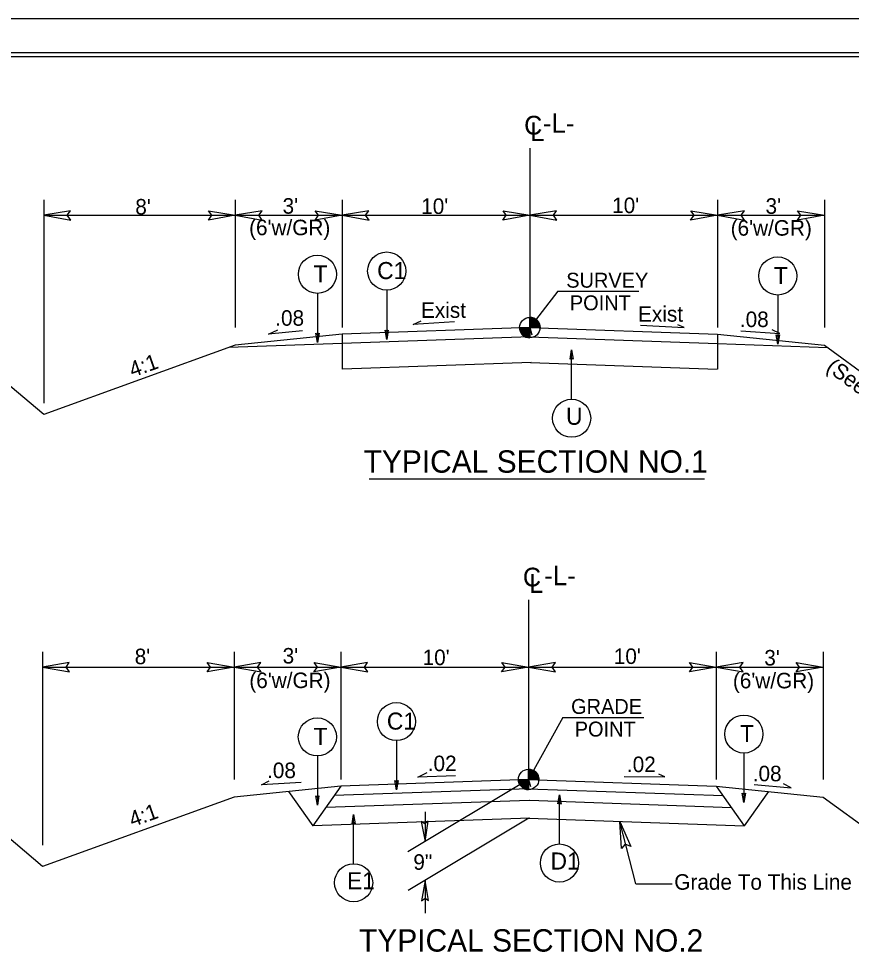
# Model space of a CAD drawing. Extents: x 573693 to 575619, y -55388 to -54288.
# Drawn here: x 574388 to 574934, y -54903 to -54288 of the extents above; entities that cross this region are included whole.
import ezdxf

# ---------------------------------------------------------------- set-up
doc = ezdxf.new("R2010")
doc.units = 0
for name, color, linetype in [('Default', 7, 'Continuous'), ('Prop Dimension', 7, 'Continuous'), ('Sheet Border Standard 30in CELL', 7, 'Continuous'), ('Sheet Cutting Line CELL', 7, 'Continuous'), ('Sheet Plot Border Inside CELL', 7, 'Continuous'), ('Sheet Plot Border Outside CELL', 7, 'Continuous'), ('Typical Grade Point Symbol CELL', 7, 'Continuous'), ('Typical ID Circle CELL', 7, 'Continuous'), ('Typical Terminator CELL', 7, 'Continuous'), ('Typical Text Centerline CELL', 7, 'Continuous'), ('Typical Text Grade Point CELL', 7, 'Continuous'), ('Typical Text ID Circle CELL', 7, 'Continuous')]:
    doc.layers.add(name, color=color, linetype=linetype)

msp = doc.modelspace()

# ---------------------------------------------------------------- linework, layer by layer
at = {"layer": 'Default'}
for p, q in [((574722.78, -54373.26), (574722.78, -54490.98)), ((574403.92, -54407.2), (574403.92, -54540.5)), ((574529.59, -54407.2), (574529.59, -54490.98)), ((574599.64, -54407.2), (574599.64, -54490.98)), ((574845.92, -54407.2), (574845.92, -54490.98)), ((574915.98, -54407.2), (574915.98, -54490.98)), ((574403.92, -54417.32), (574529.59, -54417.32)), ((574529.59, -54417.32), (574599.64, -54417.32)), ((574599.64, -54417.32), (574722.78, -54417.32)), ((574722.78, -54417.32), (574845.92, -54417.32)), ((574845.92, -54417.32), (574915.98, -54417.32)), ((574722.78, -54490.98), (574724.07, -54495.66)), ((574721.96, -54669.68), (574721.96, -54787.4)), ((574403.1, -54703.62), (574403.1, -54830.51)), ((574528.77, -54703.62), (574528.77, -54787.4)), ((574598.82, -54703.62), (574598.82, -54787.4)), ((574845.1, -54703.62), (574845.1, -54787.4)), ((574915.16, -54703.62), (574915.16, -54787.4)), ((574403.1, -54713.73), (574528.77, -54713.73)), ((574528.77, -54713.73), (574598.82, -54713.73)), ((574598.82, -54713.73), (574721.96, -54713.73)), ((574721.96, -54713.73), (574845.1, -54713.73)), ((574845.1, -54713.73), (574915.16, -54713.73)), ((574721.96, -54787.4), (574642.72, -54834.92)), ((574721.96, -54787.4), (574723.25, -54792.07)), ((574654.06, -54808.55), (574654.06, -54828.12)), ((574722.2, -54812.85), (574642.95, -54860.37)), ((574654.06, -54853.71), (574654.06, -54875.21))]:
    msp.add_line(p, q, dxfattribs=at)
at = {"layer": 'Prop Dimension'}
for p, q in [((574403.92, -54548.04), (574330.25, -54485.93)), ((574599.64, -54495.32), (574529.59, -54502.54)), ((574722.78, -54490.98), (574599.64, -54495.32)), ((574599.64, -54495.32), (574599.66, -54501.45)), ((574722.78, -54490.98), (574845.92, -54495.32)), ((574845.92, -54495.32), (574915.98, -54502.54)), ((574845.92, -54495.32), (574845.93, -54501.45)), ((574599.66, -54501.45), (574525.37, -54504.06)), ((574723, -54497.11), (574599.66, -54501.45)), ((574599.66, -54501.45), (574599.71, -54518.24)), ((574722.57, -54497.1), (574845.93, -54501.44)), ((574845.92, -54501.44), (574845.92, -54518.19)), ((574845.92, -54501.44), (574917.94, -54503.97)), ((574529.59, -54502.54), (574403.92, -54548.04)), ((574915.98, -54502.54), (575050.31, -54600.76)), ((574723.59, -54513.88), (574599.92, -54518.23)), ((574723.11, -54513.86), (574845.68, -54518.18)), ((574617.38, -54590.24), (574837.3, -54590.24)), ((574403.1, -54844.45), (574329.43, -54782.34)), ((574721.96, -54787.4), (574598.82, -54791.73)), ((574721.96, -54787.4), (574845.1, -54791.73)), ((574598.82, -54791.73), (574528.77, -54798.95)), ((574564.56, -54795.26), (574580.45, -54817.84)), ((574598.82, -54791.73), (574580.45, -54817.84)), ((574722.18, -54793.53), (574594.4, -54798.02)), ((574721.75, -54793.51), (574849.52, -54798.01)), ((574845.1, -54791.73), (574915.16, -54798.95)), ((574845.1, -54791.73), (574863.46, -54817.82)), ((574879.34, -54795.26), (574863.46, -54817.82)), ((574528.77, -54798.95), (574403.1, -54844.45)), ((574722.44, -54801.12), (574588.91, -54805.81)), ((574722.61, -54801.11), (574854.98, -54805.77)), ((574915.16, -54798.95), (575049.49, -54897.18)), ((574722.86, -54812.83), (574580.45, -54817.84)), ((574722.2, -54812.85), (574863.46, -54817.82)), ((574792.41, -54855.9), (574781.77, -54814.95)), ((574792.41, -54855.9), (574816.07, -54855.9))]:
    msp.add_line(p, q, dxfattribs=at)
at = {"layer": 'Sheet Border Standard 30in CELL'}
msp.add_lwpolyline([(575359.97, -54313.39), (573859.97, -54313.39), (573859.97, -55363.39), (575359.97, -55363.39)], close=True, dxfattribs=at)
at = {"layer": 'Sheet Cutting Line CELL'}
msp.add_line((575376.97, -54288.39), (573692.97, -54288.39), dxfattribs=at)
at = {"layer": 'Sheet Plot Border Inside CELL'}
msp.add_lwpolyline([(575372.47, -54310.84), (573705.97, -54310.84), (573705.97, -55365.94), (575372.47, -55365.94)], close=True, dxfattribs=at)
at = {"layer": 'Sheet Plot Border Outside CELL'}
msp.add_lwpolyline([(575376.97, -54288.39), (573692.97, -54288.39), (573692.97, -55388.39), (575376.97, -55388.39)], close=True, dxfattribs=at)
at = {"layer": 'Typical Grade Point Symbol CELL'}
for p, q in [((574722.78, -54490.98), (574722.78, -54484.27)), ((574716.07, -54490.98), (574722.78, -54490.98)), ((574722.77, -54497.7), (574722.78, -54490.98)), ((574722.78, -54490.98), (574722.77, -54497.7)), ((574729.5, -54490.98), (574722.78, -54490.98)), ((574721.96, -54787.4), (574721.96, -54780.68)), ((574715.25, -54787.4), (574721.96, -54787.4)), ((574721.95, -54794.11), (574721.96, -54787.4)), ((574721.96, -54787.4), (574721.95, -54794.11)), ((574728.67, -54787.4), (574721.96, -54787.4))]:
    msp.add_line(p, q, dxfattribs=at)
for points in [[(574722.84, -54484.27), (574722.84, -54484.27), (574722.84, -54490.98)], [(574722.98, -54484.27), (574722.98, -54490.98)], [(574723.11, -54484.28), (574723.11, -54490.98)], [(574723.25, -54484.28), (574723.25, -54490.98)], [(574723.38, -54484.3), (574723.38, -54490.98)], [(574723.51, -54484.31), (574723.51, -54490.98)], [(574723.65, -54484.33), (574723.65, -54490.98)], [(574723.78, -54484.34), (574723.78, -54490.98)], [(574723.92, -54484.36), (574723.92, -54490.98)], [(574724.05, -54484.39), (574724.05, -54490.98)], [(574724.19, -54484.42), (574724.19, -54490.98)], [(574724.32, -54484.45), (574724.32, -54490.98)], [(574724.45, -54484.48), (574724.45, -54490.98)], [(574724.59, -54484.52), (574724.59, -54490.98)], [(574724.72, -54484.55), (574724.72, -54490.98)], [(574724.86, -54484.6), (574724.86, -54490.98)], [(574724.99, -54484.64), (574724.99, -54490.98)], [(574725.13, -54484.69), (574725.13, -54490.98)], [(574725.26, -54484.75), (574725.26, -54490.98)], [(574725.39, -54484.81), (574725.39, -54490.98)], [(574725.53, -54484.87), (574725.53, -54490.98)], [(574725.66, -54484.92), (574725.66, -54490.98)], [(574725.8, -54484.98), (574725.8, -54490.98)], [(574725.93, -54485.06), (574725.93, -54490.98)], [(574726.07, -54485.13), (574726.07, -54490.98)], [(574726.2, -54485.21), (574726.2, -54490.98)], [(574726.33, -54485.28), (574726.33, -54490.98)], [(574726.47, -54485.37), (574726.47, -54490.98)], [(574726.6, -54485.46), (574726.6, -54490.98)], [(574726.74, -54485.57), (574726.74, -54490.98)], [(574726.87, -54485.66), (574726.87, -54490.98)], [(574727.01, -54485.76), (574727.01, -54490.98)], [(574727.14, -54485.88), (574727.14, -54490.98)], [(574727.27, -54486), (574727.27, -54490.98)], [(574727.41, -54486.12), (574727.41, -54490.98)], [(574727.54, -54486.25), (574727.54, -54490.98)], [(574727.68, -54486.39), (574727.68, -54490.98)], [(574727.81, -54486.54), (574727.81, -54490.98)], [(574727.95, -54486.7), (574727.95, -54490.98)], [(574728.08, -54486.86), (574728.08, -54490.98)], [(574728.21, -54487.04), (574728.21, -54490.98)], [(574728.35, -54487.24), (574728.35, -54490.98)], [(574728.48, -54487.45), (574728.48, -54490.98)], [(574728.62, -54487.67), (574728.62, -54490.98)], [(574728.75, -54487.91), (574728.75, -54490.98)], [(574728.88, -54488.19), (574728.88, -54490.98)], [(574729.02, -54488.51), (574729.02, -54490.98)], [(574729.15, -54488.88), (574729.15, -54490.98)], [(574729.29, -54489.34), (574729.29, -54490.98)], [(574716.1, -54490.98), (574716.1, -54491.71)], [(574716.23, -54490.98), (574716.23, -54492.5)], [(574716.37, -54490.98), (574716.37, -54492.98)], [(574716.5, -54490.98), (574716.5, -54493.38)], [(574716.64, -54490.98), (574716.64, -54493.7)], [(574716.77, -54490.98), (574716.77, -54493.98)], [(574716.9, -54490.98), (574716.9, -54494.23)], [(574717.04, -54490.98), (574717.04, -54494.47)], [(574717.17, -54490.98), (574717.17, -54494.68)], [(574717.31, -54490.98), (574717.31, -54494.88)], [(574717.44, -54490.98), (574717.44, -54495.06)], [(574717.58, -54490.98), (574717.58, -54495.22)], [(574717.71, -54490.98), (574717.71, -54495.38)], [(574717.84, -54490.98), (574717.84, -54495.53)], [(574717.98, -54490.98), (574717.98, -54495.68)], [(574718.11, -54490.98), (574718.11, -54495.82)], [(574718.25, -54490.98), (574718.25, -54495.94)], [(574718.38, -54490.98), (574718.38, -54496.06)], [(574718.52, -54490.98), (574718.52, -54496.17)], [(574718.65, -54490.98), (574718.65, -54496.28)], [(574718.78, -54490.98), (574718.78, -54496.38)], [(574718.92, -54490.98), (574718.92, -54496.47)], [(574719.05, -54490.98), (574719.05, -54496.56)], [(574719.19, -54490.98), (574719.19, -54496.65)], [(574719.32, -54490.98), (574719.32, -54496.74)], [(574719.46, -54490.98), (574719.46, -54496.82)], [(574719.59, -54490.98), (574719.59, -54496.89)], [(574719.72, -54490.98), (574719.72, -54496.97)], [(574719.86, -54490.98), (574719.86, -54497.02)], [(574719.99, -54490.98), (574719.99, -54497.08)], [(574720.13, -54490.98), (574720.13, -54497.14)], [(574720.26, -54490.98), (574720.26, -54497.2)], [(574720.4, -54490.98), (574720.4, -54497.26)], [(574720.53, -54490.98), (574720.53, -54497.31)], [(574720.66, -54490.98), (574720.66, -54497.35)], [(574720.8, -54490.98), (574720.8, -54497.4)], [(574720.93, -54490.98), (574720.93, -54497.43)], [(574721.07, -54490.98), (574721.07, -54497.47)], [(574721.2, -54490.98), (574721.2, -54497.5)], [(574721.34, -54490.98), (574721.34, -54497.53)], [(574721.47, -54490.98), (574721.47, -54497.56)], [(574721.6, -54490.98), (574721.6, -54497.59)], [(574721.74, -54490.98), (574721.74, -54497.61)], [(574721.87, -54490.98), (574721.87, -54497.64)], [(574722.01, -54490.98), (574722.01, -54497.65)], [(574722.14, -54490.98), (574722.14, -54497.67)], [(574722.28, -54490.98), (574722.28, -54497.68)], [(574722.41, -54490.98), (574722.41, -54497.68)], [(574722.54, -54490.98), (574722.54, -54497.7)], [(574722.68, -54490.98), (574722.68, -54497.7), (574722.68, -54497.7)], [(574729.42, -54490.03), (574729.42, -54490.98)], [(574722.02, -54780.68), (574722.02, -54780.68), (574722.02, -54787.4)], [(574722.16, -54780.68), (574722.16, -54787.4)], [(574722.29, -54780.7), (574722.29, -54787.4)], [(574722.42, -54780.7), (574722.42, -54787.4)], [(574722.56, -54780.71), (574722.56, -54787.4)], [(574722.69, -54780.73), (574722.69, -54787.4)], [(574722.83, -54780.74), (574722.83, -54787.4)], [(574722.96, -54780.76), (574722.96, -54787.4)], [(574723.1, -54780.77), (574723.1, -54787.4)], [(574723.23, -54780.8), (574723.23, -54787.4)], [(574723.36, -54780.83), (574723.36, -54787.4)], [(574723.5, -54780.86), (574723.5, -54787.4)], [(574723.63, -54780.89), (574723.63, -54787.4)], [(574723.77, -54780.94), (574723.77, -54787.4)], [(574723.9, -54780.97), (574723.9, -54787.4)], [(574724.03, -54781.01), (574724.03, -54787.4)], [(574724.17, -54781.06), (574724.17, -54787.4)], [(574724.3, -54781.1), (574724.3, -54787.4)], [(574724.44, -54781.16), (574724.44, -54787.4)], [(574724.57, -54781.22), (574724.57, -54787.4)], [(574724.71, -54781.28), (574724.71, -54787.4)], [(574724.84, -54781.34), (574724.84, -54787.4)], [(574724.98, -54781.4), (574724.98, -54787.4)], [(574725.11, -54781.47), (574725.11, -54787.4)], [(574725.24, -54781.55), (574725.24, -54787.4)], [(574725.38, -54781.62), (574725.38, -54787.4)], [(574725.51, -54781.7), (574725.51, -54787.4)], [(574725.65, -54781.79), (574725.65, -54787.4)], [(574725.78, -54781.88), (574725.78, -54787.4)], [(574725.92, -54781.98), (574725.92, -54787.4)], [(574726.05, -54782.07), (574726.05, -54787.4)], [(574726.18, -54782.18), (574726.18, -54787.4)], [(574726.32, -54782.3), (574726.32, -54787.4)], [(574726.45, -54782.41), (574726.45, -54787.4)], [(574726.59, -54782.53), (574726.59, -54787.4)], [(574726.72, -54782.67), (574726.72, -54787.4)], [(574726.85, -54782.8), (574726.85, -54787.4)], [(574726.99, -54782.95), (574726.99, -54787.4)], [(574727.12, -54783.12), (574727.12, -54787.4)], [(574727.26, -54783.28), (574727.26, -54787.4)], [(574727.39, -54783.46), (574727.39, -54787.4)], [(574727.53, -54783.65), (574727.53, -54787.4)], [(574727.66, -54783.86), (574727.66, -54787.4)], [(574727.79, -54784.09), (574727.79, -54787.4)], [(574727.93, -54784.32), (574727.93, -54787.4)], [(574728.06, -54784.61), (574728.06, -54787.4)], [(574715.28, -54787.4), (574715.28, -54788.13)], [(574715.41, -54787.4), (574715.41, -54788.92)], [(574715.55, -54787.4), (574715.55, -54789.4)], [(574715.68, -54787.4), (574715.68, -54789.8)], [(574715.81, -54787.4), (574715.81, -54790.11)], [(574715.95, -54787.4), (574715.95, -54790.4)], [(574716.08, -54787.4), (574716.08, -54790.65)], [(574716.22, -54787.4), (574716.22, -54790.89)], [(574716.35, -54787.4), (574716.35, -54791.1)], [(574716.49, -54787.4), (574716.49, -54791.29)], [(574716.62, -54787.4), (574716.62, -54791.47)], [(574716.75, -54787.4), (574716.75, -54791.63)], [(574716.89, -54787.4), (574716.89, -54791.8)], [(574717.02, -54787.4), (574717.02, -54791.95)], [(574717.16, -54787.4), (574717.16, -54792.1)], [(574717.29, -54787.4), (574717.29, -54792.23)], [(574717.43, -54787.4), (574717.43, -54792.35)], [(574717.56, -54787.4), (574717.56, -54792.47)], [(574717.69, -54787.4), (574717.69, -54792.59)], [(574717.83, -54787.4), (574717.83, -54792.69)], [(574717.96, -54787.4), (574717.96, -54792.8)], [(574718.1, -54787.4), (574718.1, -54792.89)], [(574718.23, -54787.4), (574718.23, -54792.98)], [(574718.37, -54787.4), (574718.37, -54793.07)], [(574718.5, -54787.4), (574718.5, -54793.16)], [(574718.63, -54787.4), (574718.63, -54793.23)], [(574718.77, -54787.4), (574718.77, -54793.31)], [(574718.9, -54787.4), (574718.9, -54793.38)], [(574719.04, -54787.4), (574719.04, -54793.44)], [(574719.17, -54787.4), (574719.17, -54793.5)], [(574719.31, -54787.4), (574719.31, -54793.56)], [(574719.44, -54787.4), (574719.44, -54793.62)], [(574719.57, -54787.4), (574719.57, -54793.68)], [(574719.71, -54787.4), (574719.71, -54793.72)], [(574719.84, -54787.4), (574719.84, -54793.77)], [(574719.98, -54787.4), (574719.98, -54793.81)], [(574720.11, -54787.4), (574720.11, -54793.84)], [(574720.25, -54787.4), (574720.25, -54793.89)], [(574720.38, -54787.4), (574720.38, -54793.92)], [(574720.51, -54787.4), (574720.51, -54793.95)], [(574720.65, -54787.4), (574720.65, -54793.98)], [(574720.78, -54787.4), (574720.78, -54794.01)], [(574720.92, -54787.4), (574720.92, -54794.02)], [(574721.05, -54787.4), (574721.05, -54794.05)], [(574721.19, -54787.4), (574721.19, -54794.07)], [(574721.32, -54787.4), (574721.32, -54794.08)], [(574721.45, -54787.4), (574721.45, -54794.1)], [(574721.59, -54787.4), (574721.59, -54794.1)], [(574721.72, -54787.4), (574721.72, -54794.11)], [(574721.86, -54787.4), (574721.86, -54794.11), (574721.86, -54794.11)], [(574728.2, -54784.92), (574728.2, -54787.4)], [(574728.33, -54785.29), (574728.33, -54787.4)], [(574728.47, -54785.76), (574728.47, -54787.4)], [(574728.6, -54786.44), (574728.6, -54787.4)]]:
    msp.add_lwpolyline(points, dxfattribs=at)
for centre in [(574722.78, -54490.98), (574721.95, -54787.4)]:
    msp.add_circle(centre, 6.71, dxfattribs=at)
for centre, start, end in [((574722.78, -54490.98), 359.99048, 89.99048), ((574722.78, -54490.98), 179.99048, 269.99048), ((574721.95, -54787.4), 359.99048, 89.99048), ((574721.95, -54787.4), 179.99048, 269.99048)]:
    msp.add_arc(centre, 6.71, start, end, dxfattribs=at)
at = {"layer": 'Typical ID Circle CELL'}
for p, q in [((574583.43, -54468.53), (574583.43, -54500.84)), ((574628.9, -54466.39), (574628.9, -54498.7)), ((574885.4, -54469.62), (574885.4, -54501.93)), ((574750.2, -54537.96), (574750.2, -54505.65)), ((574635.27, -54761.94), (574635.27, -54794.25)), ((574583.39, -54772.01), (574583.39, -54804.32)), ((574863.18, -54770.17), (574863.18, -54802.48)), ((574742.2, -54829.73), (574742.2, -54797.42)), ((574607.21, -54842.69), (574607.21, -54810.38))]:
    msp.add_line(p, q, dxfattribs=at)
for centre in [(574583.43, -54456.03), (574628.9, -54453.89), (574885.4, -54457.12), (574750.2, -54550.46), (574635.27, -54749.44), (574583.39, -54759.51), (574863.18, -54757.67), (574742.2, -54842.23), (574607.21, -54855.19)]:
    msp.add_circle(centre, 12.5, dxfattribs=at)
at = {"layer": 'Typical Terminator CELL'}
for points in [[(574421.5, -54414.29), (574403.92, -54417.32), (574421.59, -54420.44), (574419.35, -54417.32)], [(574512.01, -54414.29), (574529.59, -54417.32), (574511.92, -54420.44), (574514.16, -54417.32)], [(574547.16, -54414.29), (574529.59, -54417.32), (574547.26, -54420.44), (574545.02, -54417.32)], [(574582.07, -54414.29), (574599.64, -54417.32), (574581.97, -54420.44), (574584.22, -54417.32)], [(574617.22, -54414.29), (574599.64, -54417.32), (574617.32, -54420.44), (574615.07, -54417.32)], [(574705.21, -54414.29), (574722.78, -54417.32), (574705.11, -54420.44), (574707.36, -54417.32)], [(574740.36, -54414.29), (574722.78, -54417.32), (574740.46, -54420.44), (574738.21, -54417.32)], [(574828.35, -54414.29), (574845.92, -54417.32), (574828.25, -54420.44), (574830.49, -54417.32)], [(574863.5, -54414.29), (574845.92, -54417.32), (574863.59, -54420.44), (574861.35, -54417.32)], [(574898.4, -54414.29), (574915.98, -54417.32), (574898.3, -54420.44), (574900.55, -54417.32)], [(574584.48, -54494.75), (574583.43, -54500.84), (574582.35, -54494.72), (574583.43, -54495.5)], [(574629.95, -54492.61), (574628.9, -54498.7), (574627.81, -54492.58), (574628.9, -54493.36)], [(574886.45, -54495.84), (574885.4, -54501.93), (574884.31, -54495.8), (574885.4, -54496.58)], [(574749.15, -54511.74), (574750.2, -54505.65), (574751.28, -54511.77), (574750.2, -54511)], [(574420.68, -54710.7), (574403.1, -54713.73), (574420.77, -54716.86), (574418.53, -54713.73)], [(574511.19, -54710.7), (574528.77, -54713.73), (574511.09, -54716.86), (574513.34, -54713.73)], [(574546.34, -54710.7), (574528.77, -54713.73), (574546.44, -54716.86), (574544.19, -54713.73)], [(574581.25, -54710.7), (574598.82, -54713.73), (574581.15, -54716.86), (574583.39, -54713.73)], [(574616.4, -54710.7), (574598.82, -54713.73), (574616.5, -54716.86), (574614.25, -54713.73)], [(574704.39, -54710.7), (574721.96, -54713.73), (574704.29, -54716.86), (574706.53, -54713.73)], [(574739.54, -54710.7), (574721.96, -54713.73), (574739.63, -54716.86), (574737.39, -54713.73)], [(574827.52, -54710.7), (574845.1, -54713.73), (574827.43, -54716.86), (574829.67, -54713.73)], [(574862.68, -54710.7), (574845.1, -54713.73), (574862.77, -54716.86), (574860.53, -54713.73)], [(574897.58, -54710.7), (574915.16, -54713.73), (574897.48, -54716.86), (574899.73, -54713.73)], [(574636.32, -54788.15), (574635.27, -54794.25), (574634.18, -54788.12), (574635.27, -54788.9)], [(574864.23, -54796.39), (574863.18, -54802.48), (574862.1, -54796.35), (574863.18, -54797.13)], [(574584.44, -54798.23), (574583.39, -54804.32), (574582.31, -54798.19), (574583.39, -54798.97)], [(574741.16, -54803.52), (574742.2, -54797.42), (574743.29, -54803.55), (574742.2, -54802.77)], [(574606.16, -54816.47), (574607.21, -54810.38), (574608.29, -54816.5), (574607.21, -54815.72)], [(574651.58, -54814.97), (574654.06, -54828.12), (574656.19, -54814.82), (574653.87, -54816.55)], [(574782.97, -54832.74), (574781.77, -54814.95), (574788.97, -54831.39), (574785.4, -54829.94)], [(574656.33, -54866.89), (574654.06, -54853.71), (574651.72, -54866.97), (574654.06, -54865.28)]]:
    msp.add_lwpolyline(points, close=True, dxfattribs=at)
at = {"layer": 'Typical Text Grade Point CELL'}
for p, q in [((574741.2, -54467.15), (574722.78, -54490.98)), ((574741.2, -54467.15), (574794.27, -54467.15)), ((574646.25, -54489.06), (574651.57, -54486.56)), ((574673.4, -54487.22), (574646.25, -54489.06)), ((574795.37, -54489.47), (574823.93, -54490.95)), ((574823.93, -54490.95), (574819.96, -54489.14)), ((574551.43, -54495.35), (574557.45, -54492.54)), ((574573.76, -54493.16), (574551.43, -54495.35)), ((574861.2, -54493.14), (574886.72, -54494.94)), ((574886.72, -54494.94), (574881.66, -54492.41)), ((574744.38, -54746.77), (574721.96, -54787.4)), ((574744.38, -54746.77), (574797.45, -54746.77)), ((574649.32, -54785.82), (574655.46, -54782.93)), ((574811.29, -54785.77), (574807.32, -54783.97)), ((574546.83, -54790.94), (574551.89, -54788.41)), ((574572.79, -54789.48), (574546.83, -54790.94)), ((574673.93, -54785.06), (574649.32, -54785.82)), ((574784.55, -54785.39), (574811.29, -54785.77)), ((574869.83, -54790.73), (574894.26, -54792.9)), ((574894.26, -54792.9), (574889.2, -54790.37))]:
    msp.add_line(p, q, dxfattribs=at)

# ---------------------------------------------------------------- texts
at = {"layer": 'Typical Text Centerline CELL'}
for p in [(574719.05, -54364.38), (574718.23, -54660.8)]:
    msp.add_text('C', height=12.3, dxfattribs=at).set_placement(p)
for p in [(574723.14, -54368.58), (574722.32, -54665)]:
    msp.add_text('L', height=12.31, rotation=359.9469, dxfattribs=at).set_placement(p)
at = {"layer": 'Typical Text Grade Point CELL'}
for s, height, p in [('-L-', 12.723, (574731.38, -54363.22)), ("8'", 10.179, (574463.97, -54416.81)), ("3'", 10.179, (574560.58, -54416.26)), ("10'", 10.179, (574651.52, -54416.44)), ("10'", 10.179, (574776.77, -54415.9)), ("3'", 10.179, (574877.39, -54416.34)), ("(6'w/GR)", 10.179, (574538.63, -54430.4)), ("(6'w/GR)", 10.179, (574854.51, -54430.69)), ('SURVEY', 9.787, (574746.66, -54464.81)), ('POINT', 9.787, (574749.02, -54479.64)), ('Exist', 10.179, (574651.39, -54484.62)), ('Exist', 10.179, (574793.78, -54487.13)), ('.08', 10.179, (574555.77, -54489.78)), ('.08', 10.179, (574860.56, -54490.65)), ('TYPICAL SECTION NO.1', 14.6807, (574613.74, -54586.2)), ('-L-', 12.723, (574732.19, -54659.97)), ("8'", 10.179, (574463.59, -54711.81)), ("3'", 10.179, (574560.63, -54711.37)), ("10'", 10.179, (574652.44, -54712.42)), ("10'", 10.179, (574777.84, -54711.66)), ("3'", 10.179, (574876.57, -54712.65)), ("(6'w/GR)", 10.179, (574538.78, -54727.47)), ("(6'w/GR)", 10.179, (574855.98, -54727.65)), ('GRADE', 9.787, (574749.84, -54744.43)), ('POINT', 9.787, (574752.2, -54759.26)), ('.02', 10.179, (574655.81, -54781.98)), ('.02', 10.179, (574786.46, -54782.6)), ('.08', 10.179, (574550.41, -54786.52)), ('.08', 10.179, (574869, -54788.62)), ('9"', 10.179, (574646.36, -54846.67)), ('Grade To This Line', 10.1786, (574817.53, -54859.77)), ('TYPICAL SECTION NO.2', 14.6807, (574610.73, -54900.36))]:
    msp.add_text(s, height=height, dxfattribs=at).set_placement(p)
for s, height, rotation, p in [('4:1', 10.179, 19.46257, (574462.11, -54523.76)), ('(See X-Sections)', 10.1786, 323.79168, (574916.45, -54518.64)), ('4:1', 10.179, 19.46257, (574462.05, -54818.76))]:
    msp.add_text(s, height=height, rotation=rotation, dxfattribs=at).set_placement(p)
at = {"layer": 'Typical Text ID Circle CELL'}
for s, p in [('T', (574580.9, -54461.32)), ('C1', (574622.62, -54459.18)), ('T', (574882.86, -54462.4)), ('U', (574746.52, -54554.74)), ('C1', (574629, -54754.72)), ('T', (574580.86, -54764.79)), ('T', (574860.65, -54762.95)), ('D1', (574736.35, -54846.52)), ('E1', (574602.87, -54859.47))]:
    msp.add_text(s, height=11.19, dxfattribs=at).set_placement(p)

doc.saveas('drawing.dxf')
